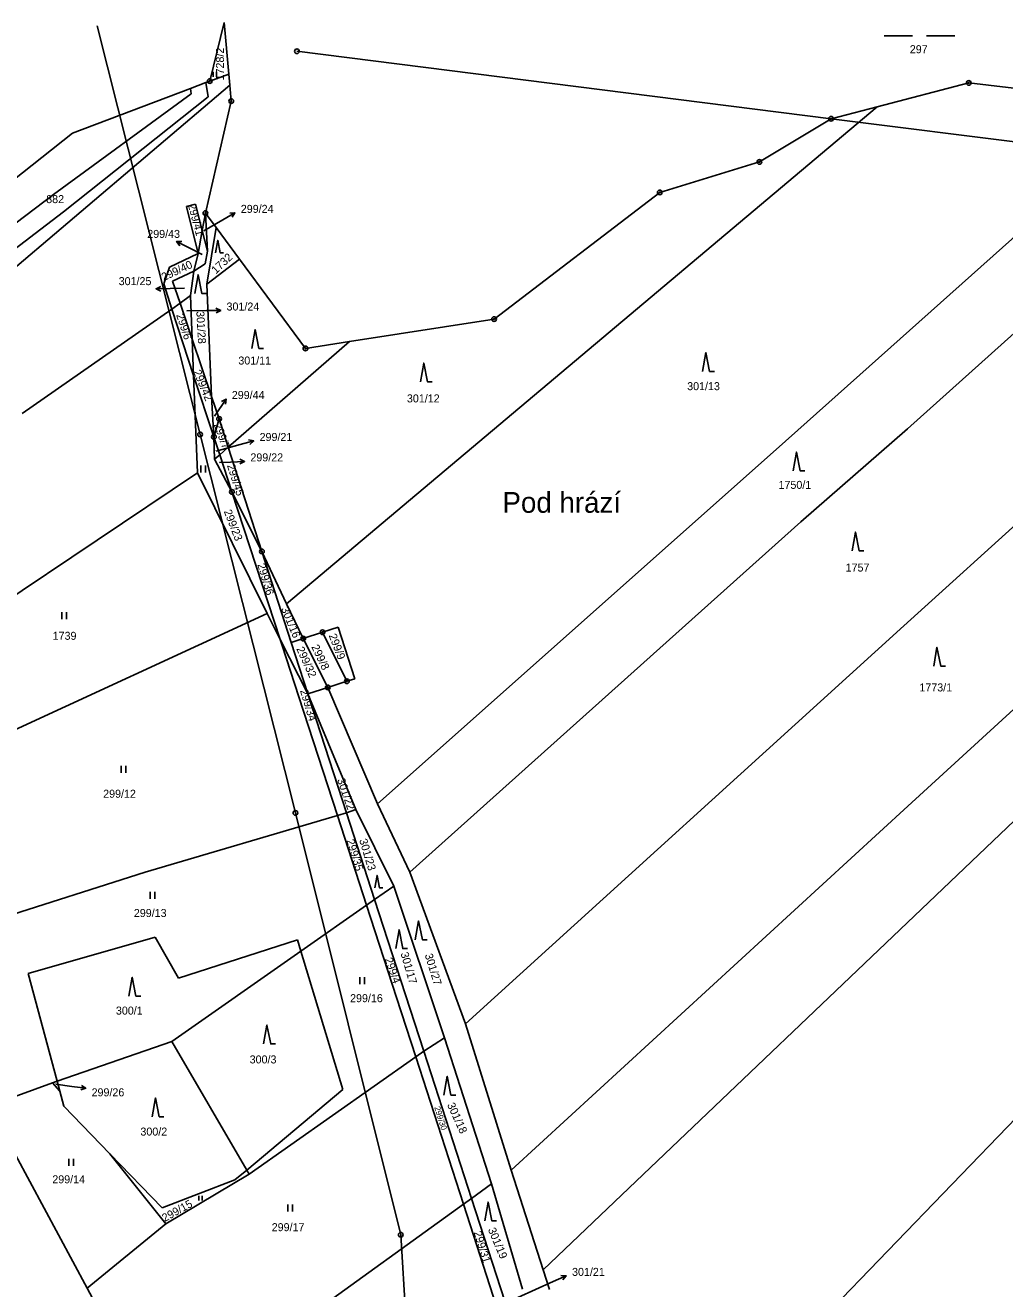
# Model space of a CAD drawing. Extents: x -762263 to -760336, y -1154405 to -1152076.
# Drawn here: x -761497.7 to -761289.6, y -1153957.5 to -1153689.1 of the extents above; entities that cross this region are included whole.
import ezdxf

# ---------------------------------------------------------------- set-up
doc = ezdxf.new("R2010")
doc.units = 0
for name, color, linetype in [('Vrstva 1', 7, 'Continuous'), ('Vrstva 12', 7, 'Continuous'), ('Vrstva 13', 7, 'Continuous'), ('Vrstva 15', 7, 'Continuous'), ('Vrstva 16', 7, 'Continuous'), ('Vrstva 17', 7, 'Continuous'), ('Vrstva 18', 7, 'Continuous'), ('Vrstva 24', 7, 'Continuous'), ('Vrstva 25', 7, 'Continuous'), ('Vrstva 26', 7, 'Continuous'), ('Vrstva 6', 7, 'Continuous')]:
    doc.layers.add(name, color=color, linetype=linetype)

msp = doc.modelspace()

# ---------------------------------------------------------------- linework, layer by layer
at = {"layer": 'Vrstva 1'}
for p, q in [((-761455.41, -1153688.48), (-761454.42, -1153699.45)), ((-761458.83, -1153704.3), (-761459.3, -1153701.24)), ((-761454.42, -1153699.45), (-761454.21, -1153701.79)), ((-761297.23, -1153701.32), (-761316.66, -1153706.37)), ((-761297.23, -1153701.32), (-761262.96, -1153705.34)), ((-761462.43, -1153703.67), (-761491.67, -1153725)), ((-761462.58, -1153702.49), (-761462.43, -1153703.67)), ((-761454.21, -1153701.79), (-761453.91, -1153705.17)), ((-761489.51, -1153728.71), (-761458.83, -1153704.3)), ((-761453.91, -1153705.17), (-761459.4, -1153728.97)), ((-761316.66, -1153706.37), (-761326.49, -1153708.93)), ((-761341.7, -1153718.11), (-761326.49, -1153708.93)), ((-761362.87, -1153724.58), (-761341.7, -1153718.11)), ((-761491.67, -1153725), (-761520.83, -1153747.19)), ((-761398.05, -1153751.51), (-761362.87, -1153724.58)), ((-761463.42, -1153727.56), (-761461.48, -1153727.07)), ((-761460.9, -1153737.53), (-761463.42, -1153727.56)), ((-761461.48, -1153727.07), (-761460.05, -1153732.71)), ((-761517.69, -1153750.19), (-761489.51, -1153728.71)), ((-761458.96, -1153737.04), (-761459.4, -1153728.97)), ((-761459.4, -1153728.97), (-761457.14, -1153732.03)), ((-761460.05, -1153732.71), (-761458.96, -1153737.04)), ((-761457.14, -1153732.03), (-761452.17, -1153738.75)), ((-761467.05, -1153740.46), (-761460.9, -1153737.53)), ((-761458.96, -1153737.04), (-761459.45, -1153739.77)), ((-761452.17, -1153738.75), (-761438.15, -1153757.73)), ((-761468.25, -1153744.04), (-761467.05, -1153740.46)), ((-761461.82, -1153741.32), (-761466.35, -1153743.41)), ((-761459.45, -1153739.77), (-761461.82, -1153741.32)), ((-761468.25, -1153744.04), (-761466.5, -1153749.37)), ((-761466.35, -1153743.41), (-761464.75, -1153748.15)), ((-761466.5, -1153749.37), (-761461.89, -1153763.45)), ((-761464.75, -1153748.15), (-761462.19, -1153755.76)), ((-761428.79, -1153756.28), (-761398.05, -1153751.51)), ((-761462.19, -1153755.76), (-761458.08, -1153767.94)), ((-761438.15, -1153757.73), (-761428.79, -1153756.28)), ((-761461.89, -1153763.45), (-761457.6, -1153776.53)), ((-761458.08, -1153767.94), (-761456.47, -1153772.7)), ((-761456.47, -1153772.7), (-761457.6, -1153776.53)), ((-761456.47, -1153772.7), (-761454.53, -1153778.73)), ((-761457.6, -1153776.53), (-761456.36, -1153780.32)), ((-761454.53, -1153778.73), (-761447.4, -1153800.87)), ((-761456.36, -1153780.32), (-761453.77, -1153788.21)), ((-761453.77, -1153788.21), (-761447.4, -1153800.87)), ((-761453.77, -1153788.21), (-761443.5, -1153819.55)), ((-761441.18, -1153820.2), (-761447.4, -1153800.87)), ((-761443.5, -1153819.55), (-761443.08, -1153820.82)), ((-761438.6, -1153819.37), (-761441.18, -1153820.2)), ((-761434.51, -1153818.04), (-761438.6, -1153819.37)), ((-761438.6, -1153819.37), (-761433.41, -1153829.77)), ((-761431.19, -1153816.97), (-761434.51, -1153818.04)), ((-761429.32, -1153828.45), (-761434.51, -1153818.04)), ((-761427.65, -1153827.91), (-761431.19, -1153816.97)), ((-761439.54, -1153831.76), (-761443.08, -1153820.82)), ((-761437.64, -1153831.14), (-761433.41, -1153829.77)), ((-761433.41, -1153829.77), (-761429.32, -1153828.45)), ((-761429.32, -1153828.45), (-761427.65, -1153827.91)), ((-761439.54, -1153831.76), (-761431.36, -1153856.94)), ((-761437.64, -1153831.14), (-761429.45, -1153856.37)), ((-761431.36, -1153856.94), (-761425.16, -1153876.04)), ((-761429.45, -1153856.37), (-761423.45, -1153874.84)), ((-761423.45, -1153874.84), (-761416.89, -1153895.05)), ((-761425.16, -1153876.04), (-761418.79, -1153895.67)), ((-761497.02, -1153890.51), (-761470.03, -1153882.83)), ((-761470.03, -1153882.83), (-761465.08, -1153891.53)), ((-761465.08, -1153891.53), (-761439.8, -1153883.42)), ((-761439.8, -1153883.42), (-761439.09, -1153885.79)), ((-761439.09, -1153885.79), (-761430.23, -1153915.19)), ((-761490.9, -1153913.41), (-761497.02, -1153890.51)), ((-761418.79, -1153895.67), (-761414.72, -1153908.24)), ((-761416.89, -1153895.05), (-761413.01, -1153907.04)), ((-761413.01, -1153907.04), (-761402.87, -1153938.33)), ((-761414.72, -1153908.24), (-761404.57, -1153939.56)), ((-761490.32, -1153915.57), (-761490.9, -1153913.41)), ((-761489.48, -1153918.72), (-761490.32, -1153915.57)), ((-761430.23, -1153915.19), (-761450.6, -1153932.3)), ((-761479.67, -1153928.87), (-761489.48, -1153918.72)), ((-761468.57, -1153940.35), (-761479.67, -1153928.87)), ((-761450.6, -1153932.3), (-761453.11, -1153934.41)), ((-761453.11, -1153934.41), (-761468.57, -1153940.35)), ((-761404.57, -1153939.56), (-761397.52, -1153961.33)), ((-761402.87, -1153938.33), (-761395.8, -1153960.17))]:
    msp.add_line(p, q, dxfattribs=at)
at = {"layer": 'Vrstva 12'}
for p, q in [((-761482.42, -1153689.16), (-761460.53, -1153776.01)), ((-761326.49, -1153708.93), (-761439.94, -1153694.6)), ((-761220.76, -1153722.27), (-761326.49, -1153708.93)), ((-761460.53, -1153776.01), (-761440.26, -1153856.41)), ((-761440.26, -1153856.41), (-761417.88, -1153946.05)), ((-761417.88, -1153946.05), (-761412.56, -1154033.02))]:
    msp.add_line(p, q, dxfattribs=at)
at = {"layer": 'Vrstva 13'}
for p, q in [((-761458.47, -1153700.93), (-761455.41, -1153688.48)), ((-761462.58, -1153702.49), (-761459.3, -1153701.24)), ((-761459.3, -1153701.24), (-761458.47, -1153700.93)), ((-761487.61, -1153711.97), (-761462.58, -1153702.49)), ((-761487.61, -1153711.97), (-761502.71, -1153723.99)), ((-761484.5, -1153957.41), (-761502.8, -1153923.42)), ((-761480.48, -1153964.88), (-761484.5, -1153957.41))]:
    msp.add_line(p, q, dxfattribs=at)
at = {"layer": 'Vrstva 16'}
for p, q in [((-761459.72, -1153732.77), (-761455.7, -1153730.44)), ((-761453.106, -1153728.932), (-761455.7, -1153730.44)), ((-761465.515, -1153735.003), (-761462.85, -1153736.38)), ((-761460.08, -1153737.81), (-761462.85, -1153736.38)), ((-761469.88, -1153745.059), (-761466.88, -1153745.01)), ((-761463.81, -1153744.96), (-761466.88, -1153745.01)), ((-761463.32, -1153749.72), (-761459.14, -1153749.7)), ((-761456.14, -1153749.683), (-761459.14, -1153749.7)), ((-761455.015, -1153768.481), (-761456.66, -1153770.99)), ((-761457.43, -1153772.16), (-761456.66, -1153770.99)), ((-761457.13, -1153779.53), (-761452.02, -1153778.17)), ((-761449.121, -1153777.4), (-761452.02, -1153778.17)), ((-761456.43, -1153781.98), (-761454.07, -1153781.87)), ((-761451.073, -1153781.73), (-761454.07, -1153781.87)), ((-761491.2, -1153914.04), (-761487.78, -1153914.52)), ((-761484.81, -1153914.94), (-761487.78, -1153914.52)), ((-761393.02, -1153959.36), (-761385.48, -1153956.01)), ((-761382.739, -1153954.791), (-761385.48, -1153956.01))]:
    msp.add_line(p, q, dxfattribs=at)
for points in [[(-761454.222, -1153729.003), (-761453.106, -1153728.932), (-761453.72, -1153729.867)], [(-761464.856, -1153735.906), (-761465.515, -1153735.003), (-761464.397, -1153735.018)], [(-761468.872, -1153745.542), (-761469.88, -1153745.059), (-761468.888, -1153744.542)], [(-761457.143, -1153749.189), (-761456.14, -1153749.683), (-761457.137, -1153750.189)], [(-761455.982, -1153769.043), (-761455.015, -1153768.481), (-761455.145, -1153769.591)], [(-761450.215, -1153777.173), (-761449.121, -1153777.4), (-761449.959, -1153778.14)], [(-761452.095, -1153781.277), (-761451.073, -1153781.73), (-761452.049, -1153782.276)], [(-761485.73, -1153914.305), (-761484.81, -1153914.94), (-761485.87, -1153915.295)], [(-761383.856, -1153954.74), (-761382.739, -1153954.791), (-761383.449, -1153955.654)]]:
    msp.add_lwpolyline(points, dxfattribs=at)
at = {"layer": 'Vrstva 24'}
for centre, radius in [((-761458.47, -1153700.93), 0.5), ((-761458.47, -1153700.93), 0.1), ((-761297.23, -1153701.32), 0.5), ((-761297.23, -1153701.32), 0.1), ((-761453.91, -1153705.17), 0.5), ((-761453.91, -1153705.17), 0.1), ((-761326.49, -1153708.93), 0.5), ((-761326.49, -1153708.93), 0.1), ((-761341.7, -1153718.11), 0.5), ((-761341.7, -1153718.11), 0.1), ((-761362.87, -1153724.58), 0.5), ((-761362.87, -1153724.58), 0.1), ((-761459.4, -1153728.97), 0.5), ((-761459.4, -1153728.97), 0.1), ((-761398.05, -1153751.51), 0.5), ((-761398.05, -1153751.51), 0.1), ((-761438.15, -1153757.73), 0.5), ((-761438.15, -1153757.73), 0.1), ((-761456.47, -1153772.7), 0.5), ((-761456.47, -1153772.7), 0.1), ((-761457.6, -1153776.53), 0.5), ((-761457.6, -1153776.53), 0.1), ((-761453.77, -1153788.21), 0.5), ((-761453.77, -1153788.21), 0.1), ((-761447.4, -1153800.87), 0.5), ((-761447.4, -1153800.87), 0.1), ((-761438.6, -1153819.37), 0.5), ((-761438.6, -1153819.37), 0.1), ((-761434.51, -1153818.04), 0.5), ((-761434.51, -1153818.04), 0.1), ((-761433.41, -1153829.77), 0.5), ((-761433.41, -1153829.77), 0.1), ((-761429.32, -1153828.45), 0.5), ((-761429.32, -1153828.45), 0.1)]:
    msp.add_circle(centre, radius, dxfattribs=at)
at = {"layer": 'Vrstva 25'}
for p, q in [((-761315.21, -1153691.28), (-761309.21, -1153691.28)), ((-761306.21, -1153691.28), (-761300.21, -1153691.28)), ((-761457.725, -1153700), (-761457.725, -1153698.995)), ((-761457.055, -1153700), (-761457.055, -1153698.995)), ((-761460.37, -1153784.08), (-761460.37, -1153782.58)), ((-761459.37, -1153784.08), (-761459.37, -1153782.58)), ((-761489.92, -1153815.25), (-761489.92, -1153813.75)), ((-761488.92, -1153815.25), (-761488.92, -1153813.75)), ((-761477.28, -1153847.91), (-761477.28, -1153846.41)), ((-761476.28, -1153847.91), (-761476.28, -1153846.41)), ((-761471.14, -1153874.71), (-761471.14, -1153873.21)), ((-761470.14, -1153874.71), (-761470.14, -1153873.21)), ((-761426.59, -1153892.82), (-761426.59, -1153891.32)), ((-761425.59, -1153892.82), (-761425.59, -1153891.32)), ((-761488.42, -1153931.4), (-761488.42, -1153929.9)), ((-761487.42, -1153931.4), (-761487.42, -1153929.9)), ((-761460.765, -1153938.79), (-761460.765, -1153937.785)), ((-761460.095, -1153938.79), (-761460.095, -1153937.785)), ((-761441.89, -1153941.13), (-761441.89, -1153939.63)), ((-761440.89, -1153941.13), (-761440.89, -1153939.63))]:
    msp.add_line(p, q, dxfattribs=at)
for points in [[(-761457.239, -1153737.43), (-761456.77, -1153734.75), (-761456.234, -1153737.43), (-761455.564, -1153737.43)], [(-761461.65, -1153746.08), (-761460.95, -1153742.08), (-761460.15, -1153746.08), (-761459.15, -1153746.08)], [(-761449.54, -1153757.73), (-761448.84, -1153753.73), (-761448.04, -1153757.73), (-761447.04, -1153757.73)], [(-761353.77, -1153762.6), (-761353.07, -1153758.6), (-761352.27, -1153762.6), (-761351.27, -1153762.6)], [(-761413.7, -1153764.84), (-761413, -1153760.84), (-761412.2, -1153764.84), (-761411.2, -1153764.84)], [(-761334.54, -1153783.77), (-761333.84, -1153779.77), (-761333.04, -1153783.77), (-761332.04, -1153783.77)], [(-761321.99, -1153800.76), (-761321.29, -1153796.76), (-761320.49, -1153800.76), (-761319.49, -1153800.76)], [(-761304.68, -1153825.21), (-761303.98, -1153821.21), (-761303.18, -1153825.21), (-761302.18, -1153825.21)], [(-761423.379, -1153872.37), (-761422.91, -1153869.69), (-761422.374, -1153872.37), (-761421.704, -1153872.37)], [(-761418.96, -1153885.24), (-761418.26, -1153881.24), (-761417.46, -1153885.24), (-761416.46, -1153885.24)], [(-761414.8, -1153883.37), (-761414.1, -1153879.37), (-761413.3, -1153883.37), (-761412.3, -1153883.37)], [(-761475.64, -1153895.35), (-761474.94, -1153891.35), (-761474.14, -1153895.35), (-761473.14, -1153895.35)], [(-761447.02, -1153905.52), (-761446.32, -1153901.52), (-761445.52, -1153905.52), (-761444.52, -1153905.52)], [(-761408.72, -1153916.38), (-761408.02, -1153912.38), (-761407.22, -1153916.38), (-761406.22, -1153916.38)], [(-761470.71, -1153920.98), (-761470.01, -1153916.98), (-761469.21, -1153920.98), (-761468.21, -1153920.98)], [(-761400.03, -1153943.1), (-761399.33, -1153939.1), (-761398.53, -1153943.1), (-761397.53, -1153943.1)]]:
    msp.add_lwpolyline(points, dxfattribs=at)
at = {"layer": 'Vrstva 26'}
for centre in [(-761439.94, -1153694.6), (-761460.53, -1153776.01), (-761440.26, -1153856.41), (-761417.88, -1153946.05)]:
    msp.add_circle(centre, 0.5, dxfattribs=at)
at = {"layer": 'Vrstva 6'}
for p, q in [((-761458.47, -1153700.93), (-761454.42, -1153699.45)), ((-761454.21, -1153701.79), (-761513.86, -1153752.5)), ((-761442.16, -1153812.03), (-761316.66, -1153706.37)), ((-761240.46, -1153712.08), (-761310.21, -1153774.82)), ((-761273.91, -1153721.86), (-761338.17, -1153779.18)), ((-761459.4, -1153728.97), (-761460.05, -1153732.71)), ((-761460.05, -1153732.71), (-761460.9, -1153737.53)), ((-761459.09, -1153744.1), (-761457.14, -1153732.03)), ((-761218.65, -1153732.82), (-761311, -1153816.67)), ((-761460.9, -1153737.53), (-761461.82, -1153741.32)), ((-761459.09, -1153744.1), (-761452.17, -1153738.75)), ((-761461.82, -1153741.32), (-761462.55, -1153746.48)), ((-761458.08, -1153767.94), (-761459.09, -1153744.1)), ((-761464.75, -1153748.15), (-761462.55, -1153746.48)), ((-761462.55, -1153746.48), (-761462.19, -1153755.76)), ((-761498.3, -1153771.59), (-761466.5, -1153749.37)), ((-761466.5, -1153749.37), (-761464.75, -1153748.15)), ((-761462.19, -1153755.76), (-761461.89, -1153763.45)), ((-761454.53, -1153778.73), (-761428.79, -1153756.28)), ((-761461.89, -1153763.45), (-761461.07, -1153784.2)), ((-761457.6, -1153776.53), (-761458.08, -1153767.94)), ((-761457.44, -1153781.27), (-761457.6, -1153776.53)), ((-761310.21, -1153774.82), (-761332.93, -1153794.58)), ((-761456.36, -1153780.32), (-761454.53, -1153778.73)), ((-761338.17, -1153779.18), (-761422.86, -1153854.51)), ((-761226.53, -1153778.32), (-761310.15, -1153855)), ((-761457.44, -1153781.27), (-761456.36, -1153780.32)), ((-761453.77, -1153788.21), (-761457.44, -1153781.27)), ((-761534.69, -1153833.47), (-761461.07, -1153784.2)), ((-761461.07, -1153784.2), (-761446.29, -1153814.02)), ((-761332.93, -1153794.58), (-761415.96, -1153869)), ((-761442.16, -1153812.03), (-761447.4, -1153800.87)), ((-761527.03, -1153851.32), (-761446.29, -1153814.02)), ((-761446.29, -1153814.02), (-761443.5, -1153819.55)), ((-761438.6, -1153819.37), (-761442.16, -1153812.03)), ((-761311, -1153816.67), (-761404.12, -1153901.21)), ((-761443.5, -1153819.55), (-761437.64, -1153831.14)), ((-761437.64, -1153831.14), (-761441.18, -1153820.2)), ((-761422.86, -1153854.51), (-761433.41, -1153829.77)), ((-761427.44, -1153855.72), (-761437.64, -1153831.14)), ((-761431.36, -1153856.94), (-761472.22, -1153869)), ((-761429.45, -1153856.37), (-761431.36, -1153856.94)), ((-761427.44, -1153855.72), (-761429.45, -1153856.37)), ((-761427.44, -1153855.72), (-761419.38, -1153871.99)), ((-761422.86, -1153854.51), (-761415.96, -1153869)), ((-761310.15, -1153855), (-761394.43, -1153932.3)), ((-761387.61, -1153953.52), (-761286.03, -1153856.59)), ((-761472.22, -1153869), (-761515.66, -1153882.92)), ((-761404.12, -1153901.21), (-761415.96, -1153869)), ((-761423.45, -1153874.84), (-761419.38, -1153871.99)), ((-761419.38, -1153871.99), (-761408.63, -1153904.24)), ((-761425.16, -1153876.04), (-761423.45, -1153874.84)), ((-761425.16, -1153876.04), (-761439.09, -1153885.79)), ((-761466.51, -1153905), (-761439.09, -1153885.79)), ((-761394.43, -1153932.3), (-761404.12, -1153901.21)), ((-761490.9, -1153913.41), (-761466.51, -1153905)), ((-761466.51, -1153905), (-761450.6, -1153932.3)), ((-761413.01, -1153907.04), (-761408.63, -1153904.24)), ((-761408.63, -1153904.24), (-761398.58, -1153935.24)), ((-761414.72, -1153908.24), (-761413.01, -1153907.04)), ((-761450.09, -1153933.18), (-761414.72, -1153908.24)), ((-761491.88, -1153913.75), (-761490.9, -1153913.41)), ((-761491.88, -1153913.75), (-761504.41, -1153918.34)), ((-761490.32, -1153915.57), (-761491.88, -1153913.75)), ((-761287.07, -1153921.16), (-761348.55, -1153984.75)), ((-761467.79, -1153943.74), (-761479.67, -1153928.87)), ((-761450.6, -1153932.3), (-761450.09, -1153933.18)), ((-761387.61, -1153953.52), (-761394.43, -1153932.3)), ((-761467.79, -1153943.74), (-761450.09, -1153933.18)), ((-761398.58, -1153935.24), (-761402.87, -1153938.33)), ((-761398.58, -1153935.24), (-761392.04, -1153957.63)), ((-761404.57, -1153939.56), (-761470.34, -1153986.97)), ((-761402.87, -1153938.33), (-761404.57, -1153939.56)), ((-761484.5, -1153957.41), (-761467.79, -1153943.74)), ((-761386.31, -1153957.66), (-761387.61, -1153953.52))]:
    msp.add_line(p, q, dxfattribs=at)

# ---------------------------------------------------------------- texts
at = {"layer": 'Vrstva 15'}
msp.add_text('Pod hrází', height=4.4, dxfattribs=at).set_placement((-761396.285, -1153792.65))
at = {"layer": 'Vrstva 16'}
for s, p in [('299/24', (-761451.873, -1153728.93)), ('299/43', (-761471.744, -1153734.25)), ('301/25', (-761477.816, -1153744.29)), ('301/24', (-761454.903, -1153749.68)), ('299/44', (-761453.783, -1153768.48)), ('299/21', (-761447.883, -1153777.4)), ('299/22', (-761449.833, -1153781.73)), ('299/26', (-761483.573, -1153916.64)), ('301/21', (-761381.503, -1153954.79))]:
    msp.add_text(s, height=1.7, dxfattribs=at).set_placement(p)
at = {"layer": 'Vrstva 17'}
msp.add_text('882', height=1.7, dxfattribs=at).set_placement((-761493.214, -1153726.86))
at = {"layer": 'Vrstva 18'}
for s, height, p in [('297', 1.7, (-761309.753, -1153695.01)), ('299/24', 0.1, (-761459.971, -1153732.77)), ('299/43', 0.1, (-761460.332, -1153737.81)), ('301/25', 0.1, (-761464.046, -1153744.96)), ('301/24', 0.1, (-761463.553, -1153749.72)), ('301/11', 1.7, (-761452.392, -1153761.15)), ('301/13', 1.7, (-761357.047, -1153766.6)), ('301/12', 1.7, (-761416.584, -1153769.2)), ('299/44', 0.1, (-761457.677, -1153772.16)), ('299/21', 0.1, (-761457.361, -1153779.53)), ('299/22', 0.1, (-761456.685, -1153781.98)), ('1750/1', 1.7, (-761337.64, -1153787.57)), ('1757', 1.7, (-761323.382, -1153805.14)), ('1739', 1.7, (-761491.842, -1153819.64)), ('1773/1', 1.7, (-761307.713, -1153830.61)), ('299/12', 1.7, (-761481.112, -1153853.2)), ('299/13', 1.7, (-761474.595, -1153878.54)), ('299/16', 1.7, (-761428.658, -1153896.64)), ('300/1', 1.7, (-761478.406, -1153899.27)), ('300/3', 1.7, (-761449.991, -1153909.65)), ('299/26', 0.1, (-761491.451, -1153914.04)), ('300/2', 1.7, (-761473.197, -1153924.98)), ('299/14', 1.7, (-761491.918, -1153935.12)), ('299/17', 1.7, (-761445.308, -1153945.29))]:
    msp.add_text(s, height=height, dxfattribs=at).set_placement(p)
for s, height, rotation, p in [('1728/2', 1.7, 90.01167, (-761455.439, -1153700.788)), ('299/41', 1.7, 284.93191, (-761463.122, -1153727.232)), ('1732', 1.7, 43.14372, (-761457.173, -1153742.012)), ('299/40', 1.7, 25.09555, (-761468.264, -1153743.451)), ('299/6', 1.7, 288.42695, (-761465.638, -1153750.633)), ('301/28', 1.7, 273.18628, (-761461.331, -1153749.844)), ('299/42', 1.7, 292.66684, (-761462.015, -1153762.67)), ('299/7', 1.7, 290.26042, (-761457.65, -1153773.938)), ('299/45', 1.7, 287.73941, (-761454.833, -1153782.599)), ('299/23', 1.7, 291.23445, (-761455.518, -1153792.329)), ('299/36', 1.7, 286.59349, (-761448.373, -1153803.665)), ('301/16', 1.7, 292.55225, (-761443.358, -1153813.021)), ('299/9', 1.7, 291.17715, (-761433.224, -1153818.721)), ('299/32', 1.7, 294.5576, (-761440.121, -1153821.547)), ('299/8', 1.7, 295.53163, (-761436.94, -1153821.128)), ('299/34', 1.7, 286.36431, (-761439.307, -1153830.43)), ('301/22', 1.7, 289.1145, (-761431.441, -1153849.377)), ('299/35', 1.7, 287.28104, (-761429.456, -1153862.275)), ('301/23', 1.7, 286.70808, (-761426.734, -1153862.182)), ('301/17', 1.7, 286.19242, (-761417.956, -1153886.259)), ('301/27', 1.7, 287.33833, (-761412.829, -1153886.586)), ('299/4', 1.7, 289.45828, (-761421.338, -1153887.484)), ('299/30', 1.27, 287.62481, (-761410.795, -1153918.991)), ('301/18', 1.7, 294.32842, (-761408.087, -1153918.416)), ('299/15', 1.7, 29.04896, (-761468.035, -1153943.361)), ('299/31', 1.7, 287.10915, (-761402.418, -1153945.549)), ('301/19', 1.7, 292.66684, (-761399.404, -1153944.933))]:
    msp.add_text(s, height=height, rotation=rotation, dxfattribs=at).set_placement(p)

doc.saveas('drawing.dxf')
